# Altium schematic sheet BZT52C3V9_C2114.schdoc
size 127 x 101 mm
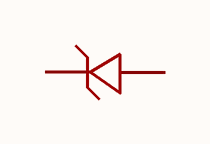
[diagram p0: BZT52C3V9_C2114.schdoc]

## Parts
ZD?  bzt52c3v9_c2114  [SOD-123_L2.8-W1.8-LS3.7-RD]  (value not drawn)

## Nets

Not connected (* = marked no-connect by the designer): ZD? 1(K) 2(A)

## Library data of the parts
ZD? = bzt52c3v9_c2114: 二极管配置:1个独立式;稳压值(标称值):3.9V;稳压值(范围):3.7V~4.1V;耗散功率(Pd):500mW;; Manufacturer: CJ(江苏长电/长晶); AddInBom: yes; ModelId: 7884390a25fb4c08947731ebfba7e3f8; ModelTransform: 144.8816,62.992,0,0,0,0,0,0,0; Diode Configuration: 1个独立式; Zener Voltage(Nom): 3.9V; Reverse Leakage Current (Ir): 3uA@1V; Pd - Power Dissipation: 500mW; Impedance(Zzt): 90Ω; Impedance(Zzk): 600Ω; Operating Junction Temperature Range: -55℃~+150℃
